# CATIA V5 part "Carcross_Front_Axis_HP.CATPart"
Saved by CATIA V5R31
Part number: Carcross_Front_Axis_HP
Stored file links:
  R:\Din II\Pfinal\CAD\Carcross_Front_Axis_HP.CATPart
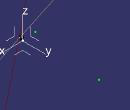
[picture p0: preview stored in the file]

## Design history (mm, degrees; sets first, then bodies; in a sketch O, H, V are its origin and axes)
AxisSystem1: origin (0, 0, 0), X (1, 0, 0), Y (0, 1, 0), Z (0, 0, 1)
Set1 "Front_Axis"
  Set2 "Left_wheel"
    Set3 "Lower_arm"
      Set4 "Lower_arm_C"
        Point1 "A": (-20, -57, 350), in AxisSystem1
        Point2 "B": (-18, -595, 330), in AxisSystem1
        Point3 "C": (211, -58, 357), in AxisSystem1
        Line1: type PtPt, FirstPoint Point1, SecondPoint Point2
        Line2: type PtPt, FirstPoint Point3, SecondPoint Point2
        Plane1 "Lower_plane": type 3Points, Element1 Point1, Element2 Point2, Element3 Point3
      Join1 "Lower_arm": Elements (Line1; Line2)
    Set5 "Upper_arm"
      Set6 "Upper_arm_C"
        Point4 "D": (-166, -99, 513), in AxisSystem1
        Point5 "E": (17, -546, 520), in AxisSystem1
        Point6 "F": (158, -124, 545), in AxisSystem1
        Line3: type PtPt, FirstPoint Point7, SecondPoint Point5
        Line4: type PtPt, FirstPoint Point6, SecondPoint Point5
        Plane2 "Upper_plane": type 3Points, Element1 Point7, Element2 Point5, Element3 Point6
        Line5 "Axis_movement": type PtDir, RefPoint Point4, Direction edge [ZX plane of AxisSystem1 | YZ plane of AxisSystem1], Start 0, End 20
        Point7 "UCA_rear_h": type OnCurve, Support Line5, Ratio 0
      Join2 "Upper_arm": Elements (Line3; Line4)
    Set7 "IC_RollCenter"
      Intersect1 "LCA_YZ": ToIntersect1 Plane1, ToIntersect2 YZ plane of AxisSystem1
      Intersect2 "UCA_YZ": ToIntersect1 Plane2, ToIntersect2 YZ plane of AxisSystem1
      Intersect3 "LCA_XZ": ToIntersect1 Plane1, ToIntersect2 ZX plane of AxisSystem1
      Intersect4 "UCA_XZ": ToIntersect1 Plane2, ToIntersect2 ZX plane of AxisSystem1
      Intersect5 "IC_YZ": ToIntersect1 Intersect1, ToIntersect2 Intersect2
      Intersect6 "IC_XZ": ToIntersect1 Intersect3, ToIntersect2 Intersect4
      Intersect7 "IC_Line": ToIntersect1 Plane1, ToIntersect2 Plane2
      Line6 "IC_Contactpatch_Line_In": type PtPt, FirstPoint Intersect5, SecondPoint Point13
      Line7 "IC_Contactpatch_Line_Out": type PtPt, FirstPoint Intersect5, SecondPoint Symmetry1
      Plane3 "IC_plane_YZ": type OffsetPt, RefPlane zx-plane, RefPoint Intersect5
      Plane4 "IC_plane_XZ": type OffsetPt, RefPlane YZ plane of AxisSystem1, RefPoint Intersect6
      Intersect8 "Roll_center": ToIntersect1 Line6, ToIntersect2 edge [ZX plane of AxisSystem1 | YZ plane of AxisSystem1]
      Intersect9: ToIntersect1 Plane1, ToIntersect2 Plane2
      Line8 "Instant_Axis": type PtPt, FirstPoint Intersect5, SecondPoint Intersect6
      Symmetry1 "Wheel_contact_right": ToTransfor Point13, Reference ZX plane of AxisSystem1
    Set8 "tie_rod"
      Set9 "tie_rod_C"
        Point8 "In": (-64, -105, 462), in AxisSystem1
        Point9 "Out": (-78, -588, 460), in AxisSystem1
        Line9: type PtPt, FirstPoint Point8, SecondPoint Point9
        Line10 "tierod_ideal": type PtPt, FirstPoint Intersect5, SecondPoint Point8, End 500
        Line11 "tierod_actual": type PtPt, LineSecondUpto Plane3, FirstPoint Point9, SecondPoint Point8, End 500
        Intersect10 "tierod_ICplane": ToIntersect1 {inverselocal InverseElem Line11}, ToIntersect2 Plane3
      Join3 "tierod": Elements Line9
    Set10 "Strut"
      Set11 "Strut_C"
        Point10 "Down": (3, -520, 370), in AxisSystem1
        Point11 "Up": (39, -166, 605), in AxisSystem1
        Line12: type PtPt, FirstPoint Point10, SecondPoint Point11
      Join4 "Strut": Elements Line12
    Set12 "Wheel"
      Set13 "Wheel_C"
        Line13 "Wheel_radius": type Angle, RefPoint Point12, Curve Z axis, Support YZ plane of AxisSystem1, Start 0, End 242.5, Angle -1.5
        Point12 "Wheel_Center": (0, -682, 405), in AxisSystem1
        Point13 "Wheel_contactpatch": type OnCurve, Support Line13, Ratio 0
    Set14 "Mangeta"
      Set15 "Mangeta_C"
        Line14: type PtPt, FirstPoint Point2, SecondPoint Point12
        Line15: type PtPt, FirstPoint Point9, SecondPoint Point12
        Line16: type PtPt, FirstPoint Point5, SecondPoint Point12
        Plane5 "Plane_mangueta": type 3Points, Element1 Point9, Element2 Point5, Element3 Point2
        Plane6 "Plane_mangueta_WC": type OffsetPt, RefPlane Plane5, RefPoint Point12
        Intersect11 "Toe_original_zero": ToIntersect1 Plane6, ToIntersect2 XY plane of AxisSystem1
        Intersect12 "Camber_original_zero": ToIntersect1 Plane6, ToIntersect2 YZ plane of AxisSystem1
    Set16 "Ackermann"
      Point14 "Wheelbase_point": type OnPlane, Support Plane7, RefPoint vertex [YZ plane of AxisSystem1 | ZX plane of AxisSystem1 | XY plane of AxisSystem1], H 2040, V 0, Direction (1, 0, 0)
      Project1 "Tierod_projection": ToProject Join3, Support Plane7
      Line17 "Ackermann_Actual": type PtPt, LineSecondUpto ZX plane of AxisSystem1, FirstPoint Intersect13, SecondPoint vertex of Project1
      Line18 "Ackermann_deseado": type PtPt, FirstPoint Intersect13, SecondPoint Point14
    Set17 "Caster_Scrub"
      Line19 "Kingpin": type PtPt, LineSecondUpto Plane7, FirstPoint Point5, SecondPoint Point2, End 1000
      Plane7 "Floor": type OffsetPt, RefPlane XY plane of AxisSystem1, RefPoint Point13
      Intersect13 "Contact_patch": ToIntersect1 Plane7, ToIntersect2 Line19
      Line20 "Scrub_radius": type PtPt, FirstPoint Point13, SecondPoint Intersect13
      Line21 "Ideal_kingpin": type PtPt, FirstPoint Point13, SecondPoint Point2, End 500
    Set18 "Setup"
      Set19 "Setup_C"
        Set20 "Tierod"
          Line22 "tierod_extension": type Tangency, RefPoint Point9, Curve Join3, Start 0, End 0.01
          Point15 "tierod_point_extension": type OnCurve, Support Line22, Ratio 1
        Set21 "LCA"
          Line23 "lca_extension": type Tangency, RefPoint Point2, Curve Line1, Start 0, End 0.01
          Point16 "lca_point_extension": type OnCurve, Support Line23, Ratio 1
        Set22 "UCA"
          Line24 "uca_extension": type Tangency, RefPoint Point5, Curve Line26, Start 0, End 0.01
          Point17 "uca_point_extension": type OnCurve, Support {inverselocal InverseElem Line24}, Ratio 1
          Line25 "line_front_rear": type PtPt, FirstPoint Point7, SecondPoint Point6
          Point18 "mipoint_front_rear": type OnCurve, Support Line25, Ratio 0.5
          Line26 "HP_direction": type PtPt, FirstPoint Point18, SecondPoint Point5
        Set23 "Mangueta"
          Line27 "lca_wc": type PtPt, FirstPoint Point16, SecondPoint Point12
          Line28 "tierod_wc": type PtPt, FirstPoint Point15, SecondPoint Point12
          Line29 "uca_wc": type PtPt, FirstPoint Point17, SecondPoint Point12
          Plane8 "Plane_outers": type 3Points, Element1 Point15, Element2 Point16, Element3 Point17
          Plane9 "Plane_outers_WC": type OffsetPt, RefPlane Plane8, RefPoint Point12
          Intersect14 "Toe_setup": ToIntersect1 Plane9, ToIntersect2 XY plane of AxisSystem1
          Intersect15 "Camber_setup": ToIntersect1 Plane9, ToIntersect2 YZ plane of AxisSystem1
  Set24 "Left_wheel_mods"
    Set25 "Lower_arm"
      Set26 "Lower_arm_C"
        Point19 "A": (-20, -57, 350), in AxisSystem1
        Point20 "B": (-18, -595, 330), in AxisSystem1
        Point21 "C": (211, -58, 357), in AxisSystem1
        Line30: type PtPt, FirstPoint Point19, SecondPoint Point20
        Line31: type PtPt, FirstPoint Point21, SecondPoint Point20
        Plane10 "Lower_plane": type 3Points, Element1 Point19, Element2 Point20, Element3 Point21
      Join5 "Lower_arm": Elements (Line30; Line31)
    Set27 "Upper_arm"
      Set28 "Upper_arm_C"
        Point22 "D": (-166, -99, 513), in AxisSystem1
        Point23 "E": (17, -489, 520), in AxisSystem1
        Point24 "F": (158, -124, 545), in AxisSystem1
        Line32: type PtPt, FirstPoint Point22, SecondPoint Point23
        Line33: type PtPt, FirstPoint Point24, SecondPoint Point23
        Plane11 "Upper_plane": type 3Points, Element1 Point22, Element2 Point23, Element3 Point24
      Join6 "Upper_arm": Elements (Line32; Line33)
    Set29 "IC_RollCenter"
      Intersect16 "LCA_YZ": ToIntersect1 Plane10, ToIntersect2 YZ plane of AxisSystem1
      Intersect17 "UCA_YZ": ToIntersect1 Plane11, ToIntersect2 YZ plane of AxisSystem1
      Intersect18 "LCA_XZ": ToIntersect1 Plane10, ToIntersect2 ZX plane of AxisSystem1
      Intersect19 "UCA_XZ": ToIntersect1 Plane11, ToIntersect2 ZX plane of AxisSystem1
      Intersect20 "IC_YZ": ToIntersect1 Intersect16, ToIntersect2 Intersect17
      Intersect21 "IC_XZ": ToIntersect1 Intersect18, ToIntersect2 Intersect19
      Intersect22 "IC_Line": ToIntersect1 Plane10, ToIntersect2 Plane11
      Line34 "IC_Contactpatch_Line_In": type PtPt, FirstPoint Intersect20, SecondPoint Point30
      Line35 "IC_Contactpatch_Line_Out": type PtPt, FirstPoint Intersect20, SecondPoint vertex of Line41
      Plane12 "IC_plane_YZ": type OffsetPt, RefPlane zx-plane, RefPoint Intersect20
      Plane13 "IC_plane_XZ": type OffsetPt, RefPlane YZ plane of AxisSystem1, RefPoint Intersect21
      Intersect23 "Roll_center": ToIntersect1 Line34, ToIntersect2 edge [ZX plane of AxisSystem1 | YZ plane of AxisSystem1]
      Intersect24: ToIntersect1 Plane10, ToIntersect2 Plane11
      Line36 "Instant_Axis": type PtPt, FirstPoint Intersect20, SecondPoint Intersect21
    Set30 "tie_rod"
      Set31 "tie_rod_C"
        Point25 "In": (-64, -105, 462), in AxisSystem1
        Point26 "Out": (-65, -549, 447), in AxisSystem1
        Line37: type PtPt, FirstPoint Point25, SecondPoint Point26
        Line38 "tierod_ideal": type PtPt, FirstPoint Intersect20, SecondPoint Point25, End 500
        Line39 "tierod_actual": type PtPt, LineSecondUpto Plane12, FirstPoint Point26, SecondPoint Point25, End 500
        Intersect25 "tierod_ICplane": ToIntersect1 {inverselocal InverseElem Line39}, ToIntersect2 Plane12
      Join7 "tierod": Elements Line37
    Set32 "Strut"
      Set33 "Strut_C"
        Point27 "Down": (3, -520, 370), in AxisSystem1
        Point28 "Up": (39, -166, 605), in AxisSystem1
        Line40: type PtPt, FirstPoint Point27, SecondPoint Point28
      Join8 "Strut": Elements Line40
    Set34 "Wheel"
      Set35 "Wheel_C"
        Line41 "Wheel_radius": type Angle, RefPoint Point29, Curve Z axis, Support YZ plane of AxisSystem1, Start 0, End 242.5, Angle -1.5
        Point29 "Wheel_Center": (0, -682, 405), in AxisSystem1
        Point30 "Wheel_contactpatch": type OnCurve, Support Line41, Ratio 0
    Set36 "Mangeta"
      Set37 "Mangeta_C"
        Line42: type PtPt, FirstPoint Point20, SecondPoint Point29
        Line43: type PtPt, FirstPoint Point26, SecondPoint Point29
        Line44: type PtPt, FirstPoint Point23, SecondPoint Point29
        Plane14: type 3Points, Element1 Point26, Element2 Point23, Element3 Point20
        Plane15: type OffsetPt, RefPlane Plane14, RefPoint Point29
    Set38 "Ackermann"
      Point31 "Wheelbase_point": type OnPlane, Support Plane16, RefPoint vertex [YZ plane of AxisSystem1 | ZX plane of AxisSystem1 | XY plane of AxisSystem1], H 2040, V 0, Direction (1, 0, 0)
      Project2 "Tierod_projection": ToProject Join7, Support Plane16
      Line45 "Ackermann_Actual": type PtPt, LineSecondUpto ZX plane of AxisSystem1, FirstPoint Intersect26, SecondPoint vertex of Project2
      Line46 "Ackermann_deseado": type PtPt, FirstPoint Intersect26, SecondPoint Point31
    Set39 "Caster_Scrub"
      Line47 "Kingpin": type PtPt, LineSecondUpto Plane16, FirstPoint Point23, SecondPoint Point20, End 1000
      Plane16 "Floor": type OffsetPt, RefPlane XY plane of AxisSystem1, RefPoint Point30
      Intersect26 "Contact_patch": ToIntersect1 Plane16, ToIntersect2 Line47
      Line48 "Scrub_radius": type PtPt, FirstPoint Point30, SecondPoint Intersect26
      Line49 "Ideal_kingpin": type PtPt, FirstPoint Point30, SecondPoint Point20, End 500
Body1 (main body)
